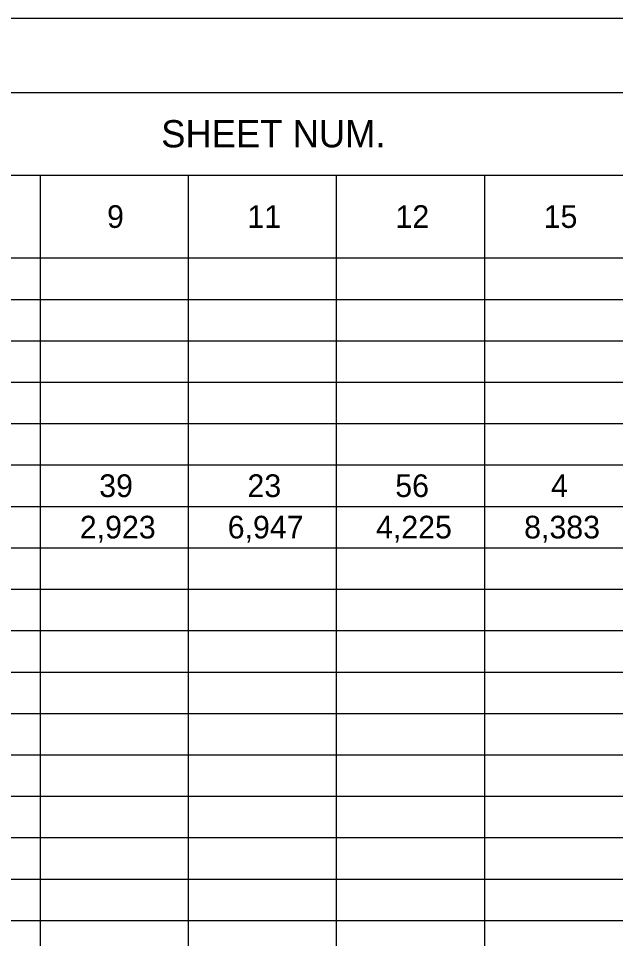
# Model space of a CAD drawing. Extents: x 0 to 34, y 0 to 22.
# Drawn here: x 4.36 to 8.4, y 15.78 to 22 of the extents above; entities that cross this region are included whole.
import ezdxf

# ---------------------------------------------------------------- set-up
doc = ezdxf.new("R2010")
doc.units = 0
for name, color, linetype in [('SH_Border', 7, 'Continuous'), ('SH_Cut_Line', 7, 'Continuous'), ('SH_Text', 7, 'Continuous')]:
    doc.layers.add(name, color=color, linetype=linetype)

msp = doc.modelspace()

# ---------------------------------------------------------------- linework, layer by layer
at = {"layer": 'SH_Border'}
msp.add_lwpolyline([(1.5, 21.5), (33.5, 21.5), (33.5, 0.5), (1.5, 0.5)], close=True, dxfattribs=at)
at = {"layer": 'SH_Cut_Line'}
msp.add_lwpolyline([(0, 0), (34, 0), (34, 22), (0, 22)], close=True, dxfattribs=at)
at = {"layer": 'SH_Text'}
for p, q in [((1.5, 21.5), (6.5084, 21.5)), ((6.5084, 21.5), (7.5101, 21.5)), ((7.5101, 21.5), (13.9825, 21.5)), ((1.5, 20.94), (6.5084, 20.94)), ((4.5051, 20.94), (4.5051, 20.66)), ((5.5067, 20.94), (5.5067, 20.66)), ((6.5084, 20.94), (7.5101, 20.94)), ((6.5084, 20.94), (6.5084, 20.66)), ((7.5101, 20.94), (11.5168, 20.94)), ((7.5101, 20.94), (7.5101, 20.66)), ((4.5051, 20.66), (4.5051, 20.38)), ((5.5067, 20.66), (5.5067, 20.38)), ((6.5084, 20.66), (6.5084, 20.38)), ((7.5101, 20.66), (7.5101, 20.38)), ((1.5, 20.38), (6.5084, 20.38)), ((4.5051, 20.38), (4.5051, 20.1)), ((5.5067, 20.38), (5.5067, 20.1)), ((6.5084, 20.38), (7.5101, 20.38)), ((6.5084, 20.38), (6.5084, 20.1)), ((7.5101, 20.38), (13.9825, 20.38)), ((7.5101, 20.38), (7.5101, 20.1)), ((1.5, 20.1), (6.5084, 20.1)), ((4.5051, 20.1), (4.5051, 18.7)), ((5.5067, 20.1), (5.5067, 18.7)), ((6.5084, 20.1), (7.5101, 20.1)), ((6.5084, 20.1), (6.5084, 18.7)), ((7.5101, 20.1), (13.9825, 20.1)), ((7.5101, 20.1), (7.5101, 18.7)), ((1.5, 19.82), (6.5084, 19.82)), ((6.5084, 19.82), (7.5101, 19.82)), ((7.5101, 19.82), (13.9825, 19.82)), ((1.5, 19.54), (6.5084, 19.54)), ((6.5084, 19.54), (7.5101, 19.54)), ((7.5101, 19.54), (13.9825, 19.54)), ((1.5, 19.26), (6.5084, 19.26)), ((6.5084, 19.26), (7.5101, 19.26)), ((7.5101, 19.26), (13.9825, 19.26)), ((1.5, 18.98), (6.5084, 18.98)), ((6.5084, 18.98), (7.5101, 18.98)), ((7.5101, 18.98), (13.9825, 18.98)), ((1.5, 18.7), (6.5084, 18.7)), ((4.5051, 18.7), (4.5051, 18.14)), ((5.5067, 18.7), (5.5067, 18.14)), ((6.5084, 18.7), (7.5101, 18.7)), ((6.5084, 18.7), (6.5084, 18.14)), ((7.5101, 18.7), (13.9825, 18.7)), ((7.5101, 18.7), (7.5101, 18.14)), ((1.5, 18.42), (6.5084, 18.42)), ((6.5084, 18.42), (7.5101, 18.42)), ((7.5101, 18.42), (13.9825, 18.42)), ((1.5, 18.14), (6.5084, 18.14)), ((4.5051, 18.14), (4.5051, 17.86)), ((5.5067, 18.14), (5.5067, 17.86)), ((6.5084, 18.14), (7.5101, 18.14)), ((6.5084, 18.14), (6.5084, 17.86)), ((7.5101, 18.14), (13.9825, 18.14)), ((7.5101, 18.14), (7.5101, 17.86)), ((1.5, 17.86), (6.5084, 17.86)), ((4.5051, 17.86), (4.5051, 17.58)), ((5.5067, 17.86), (5.5067, 17.58)), ((6.5084, 17.86), (7.5101, 17.86)), ((6.5084, 17.86), (6.5084, 17.58)), ((7.5101, 17.86), (13.9825, 17.86)), ((7.5101, 17.86), (7.5101, 17.58)), ((1.5, 17.58), (6.5084, 17.58)), ((4.5051, 17.58), (4.5051, 17.3)), ((5.5067, 17.58), (5.5067, 17.3)), ((6.5084, 17.58), (7.5101, 17.58)), ((6.5084, 17.58), (6.5084, 17.3)), ((7.5101, 17.58), (13.9825, 17.58)), ((7.5101, 17.58), (7.5101, 17.3)), ((1.5, 17.3), (6.5084, 17.3)), ((4.5051, 17.3), (4.5051, 17.02)), ((5.5067, 17.3), (5.5067, 17.02)), ((6.5084, 17.3), (7.5101, 17.3)), ((6.5084, 17.3), (6.5084, 17.02)), ((7.5101, 17.3), (13.9825, 17.3)), ((7.5101, 17.3), (7.5101, 17.02)), ((1.5, 17.02), (6.5084, 17.02)), ((4.5051, 17.02), (4.5051, 16.74)), ((5.5067, 17.02), (5.5067, 16.74)), ((6.5084, 17.02), (7.5101, 17.02)), ((6.5084, 17.02), (6.5084, 16.74)), ((7.5101, 17.02), (13.9825, 17.02)), ((7.5101, 17.02), (7.5101, 16.74)), ((1.5, 16.74), (6.5084, 16.74)), ((4.5051, 16.74), (4.5051, 16.18)), ((5.5067, 16.74), (5.5067, 16.18)), ((6.5084, 16.74), (7.5101, 16.74)), ((6.5084, 16.74), (6.5084, 16.18)), ((7.5101, 16.74), (13.9825, 16.74)), ((7.5101, 16.74), (7.5101, 16.18)), ((1.5, 16.46), (6.5084, 16.46)), ((6.5084, 16.46), (7.5101, 16.46)), ((7.5101, 16.46), (13.9825, 16.46)), ((1.5, 16.18), (6.5084, 16.18)), ((4.5051, 16.18), (4.5051, 15.9)), ((5.5067, 16.18), (5.5067, 15.9)), ((6.5084, 16.18), (7.5101, 16.18)), ((6.5084, 16.18), (6.5084, 15.9)), ((7.5101, 16.18), (13.9825, 16.18)), ((7.5101, 16.18), (7.5101, 15.9)), ((1.5, 15.9), (6.5084, 15.9)), ((4.5051, 15.9), (4.5051, 15.62)), ((5.5067, 15.9), (5.5067, 15.62)), ((6.5084, 15.9), (7.5101, 15.9)), ((6.5084, 15.9), (6.5084, 15.62)), ((7.5101, 15.9), (13.9825, 15.9)), ((7.5101, 15.9), (7.5101, 15.62))]:
    msp.add_line(p, q, dxfattribs=at)

# ---------------------------------------------------------------- texts
for s, height, p in [('SHEET NUM.', 0.184, (5.3243, 21.128)), ('9', 0.1533, (4.9582, 20.5833)), ('11', 0.15333, (5.9072, 20.5833)), ('12', 0.15333, (6.909, 20.5833)), ('15', 0.15333, (7.911, 20.5833)), ('39', 0.15333, (4.9051, 18.7633)), ('23', 0.15333, (5.9079, 18.7633)), ('56', 0.15333, (6.9073, 18.7633)), ('4', 0.1533, (7.9609, 18.7633)), ('2,923', 0.15333, (4.7739, 18.4833)), ('6,947', 0.15333, (5.7741, 18.4833)), ('4,225', 0.15333, (6.7771, 18.4833)), ('8,383', 0.15333, (7.779, 18.4833))]:
    msp.add_text(s, height=height, dxfattribs=at).set_placement(p)

doc.saveas('drawing.dxf')
